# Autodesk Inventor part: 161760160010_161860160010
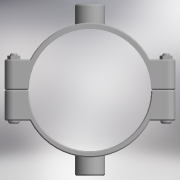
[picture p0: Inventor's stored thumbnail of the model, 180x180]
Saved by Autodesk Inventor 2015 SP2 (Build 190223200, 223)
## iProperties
Created: 2017-05
Part Number: 161760160010_161860160010
Material: Generic
Description: PLASSON DOUBLE SADDLE 160-1"
Document SubType Name: Modeling
Designer: KIM
Density: 1 g/cm^3
Appearance: Default
Author: KIM
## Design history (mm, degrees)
derived "16176.ipt"
feature "Solid1::16176.ipt"
feature "Solid2::16176.ipt"
tag "TaggingFeature1"
body "Solid1"
body "Solid2"
other parameters: "d0" = 176, "d1" = 223, "d4" = 145, "d5" = 0, "d6" = 11.15, "d7" = 223, "d8" = 0.1, "d10" = 0, "d11" = 1.6, "d20" = 1.6, "d23" = 1.6, "d36" = 15, "d37" = 12, "d38" = 88, "d39" = 0, "d40" = 3, "d41" = 5, "d42" = 0, "d44" = 3, "d45" = 0, "d46" = 1.6, "d52" = 30.291, "d53" = 21, "d54" = 0, "d55" = 25, "d57" = 0, "d58" = 172.8, "d60" = 0, "d62" = 15, "d63" = 12, "d66" = 121, "d67" = 224, "d68" = 39.3783, "d69" = 30.291, "d70" = 21, "d71" = 0, "d72" = 25, "d74" = 0, "d75" = 1.6, "B_" = 25, "G_" = 30.291, "A_" = 112, "L_" = 223, "L_1" = 145, "l_2" = 21
